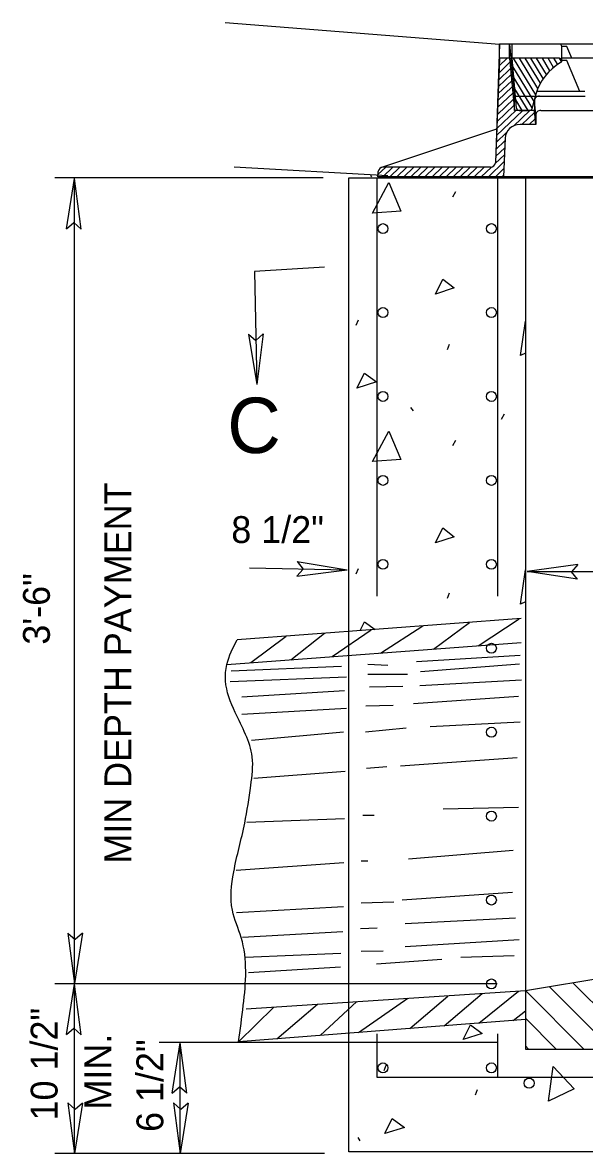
# Model space of a CAD drawing. Extents: x 0.9 to 8.1, y 0.4 to 10.5.
# Drawn here: x 0.924 to 1.927, y 5.374 to 7.395 of the extents above; entities that cross this region are included whole.
import ezdxf

# ---------------------------------------------------------------- set-up
doc = ezdxf.new("R2010")
doc.units = 0
for name, color, linetype in [('DETL-DIMS', 7, 'Continuous'), ('DETL-LINE', 7, 'Continuous'), ('DETL-NOTE', 7, 'Continuous')]:
    doc.layers.add(name, color=color, linetype=linetype)

msp = doc.modelspace()

# ---------------------------------------------------------------- linework, layer by layer
at = {"layer": 'DETL-DIMS'}
for p, q in [((1.4607, 7.1175), (0.9813, 7.1175)), ((1.002, 7.0264), (1.0163, 7.1162)), ((1.0163, 5.374), (1.0163, 7.1175)), ((1.0282, 7.026), (1.0163, 7.1162)), ((1.002, 7.0264), (1.0152, 7.0375)), ((1.0282, 7.026), (1.0152, 7.0375)), ((1.4629, 6.9579), (1.338, 6.9499)), ((1.338, 6.9499), (1.342, 6.7483)), ((1.3271, 6.8381), (1.342, 6.7483)), ((1.3271, 6.8381), (1.3405, 6.8271)), ((1.3534, 6.8386), (1.3405, 6.8271)), ((1.3534, 6.8386), (1.342, 6.7483)), ((1.414, 6.4318), (1.5038, 6.4168)), ((1.414, 6.4318), (1.425, 6.4184)), ((1.329, 6.4204), (1.5037, 6.4168)), ((1.4134, 6.4055), (1.425, 6.4184)), ((1.4134, 6.4055), (1.5038, 6.4168)), ((1.9155, 6.4263), (1.8254, 6.4138)), ((1.9153, 6.4), (1.8254, 6.4138)), ((1.8254, 6.4138), (3.481, 6.4138)), ((1.9155, 6.4263), (1.9042, 6.4132)), ((1.9153, 6.4), (1.9042, 6.4132)), ((1.0044, 5.7678), (1.0163, 5.6776)), ((1.0044, 5.7678), (1.0174, 5.7563)), ((1.0306, 5.7674), (1.0163, 5.6776)), ((1.0306, 5.7674), (1.0174, 5.7563)), ((0.9813, 5.6776), (1.7718, 5.6776)), ((1.002, 5.5864), (1.0163, 5.6763)), ((1.0282, 5.5861), (1.0163, 5.6763)), ((1.002, 5.5864), (1.0152, 5.5975)), ((1.0282, 5.5861), (1.0152, 5.5975)), ((1.1676, 5.573), (1.7718, 5.573)), ((1.1908, 5.4819), (1.2052, 5.5717)), ((1.2051, 5.374), (1.2051, 5.573)), ((1.2171, 5.4815), (1.2052, 5.5717)), ((1.1908, 5.4819), (1.2041, 5.4929)), ((1.2171, 5.4815), (1.2041, 5.4929)), ((1.0044, 5.4642), (1.0163, 5.374)), ((1.0044, 5.4642), (1.0174, 5.4527)), ((1.0306, 5.4638), (1.0163, 5.374)), ((1.0306, 5.4638), (1.0174, 5.4527)), ((1.1932, 5.4642), (1.2051, 5.374)), ((1.1932, 5.4642), (1.2062, 5.4527)), ((1.2195, 5.4638), (1.2051, 5.374)), ((1.2195, 5.4638), (1.2062, 5.4527)), ((1.4629, 5.374), (0.9813, 5.374))]:
    msp.add_line(p, q, dxfattribs=at)
at = {"layer": 'DETL-LINE'}
for p, q in [((1.2854, 7.395), (1.776, 7.3567)), ((1.776, 7.3567), (1.7683, 7.1447)), ((1.7982, 7.3567), (1.776, 7.3567)), ((1.7938, 7.3313), (1.7938, 7.3567)), ((1.7938, 7.3567), (1.8023, 7.2636)), ((1.8827, 7.3567), (1.7982, 7.3567)), ((1.7982, 7.3313), (1.7982, 7.3567)), ((2.6296, 7.3567), (1.8827, 7.3567)), ((1.8871, 7.3271), (1.8871, 7.3525)), ((1.896, 7.3525), (1.8871, 7.3525)), ((1.905, 7.3313), (1.896, 7.3525)), ((1.7749, 7.3055), (1.7944, 7.3241)), ((1.7754, 7.3179), (1.7895, 7.3313)), ((1.7759, 7.3304), (1.7769, 7.3313)), ((1.7938, 7.3313), (1.776, 7.3313)), ((1.7938, 7.3313), (1.8023, 7.2382)), ((1.8064, 7.242), (1.7982, 7.3313)), ((1.8827, 7.3313), (1.7982, 7.3313)), ((1.8375, 7.2543), (1.7995, 7.3168)), ((1.8406, 7.266), (1.801, 7.3313)), ((1.8442, 7.277), (1.8113, 7.3313)), ((1.8487, 7.2865), (1.8216, 7.3313)), ((1.8539, 7.2949), (1.8318, 7.3313)), ((1.8596, 7.3024), (1.8421, 7.3313)), ((1.8659, 7.3091), (1.8524, 7.3313)), ((1.8725, 7.315), (1.8626, 7.3313)), ((1.8797, 7.3202), (1.8729, 7.3313)), ((1.8868, 7.3254), (1.8832, 7.3313)), ((2.0072, 7.3313), (1.8871, 7.3313)), ((1.896, 7.3271), (1.8871, 7.3271)), ((1.9192, 7.272), (1.896, 7.3271)), ((1.7739, 7.2806), (1.7965, 7.302)), ((1.7744, 7.293), (1.7954, 7.313)), ((1.8343, 7.2426), (1.8014, 7.2969)), ((1.7729, 7.2556), (1.7985, 7.28)), ((1.7734, 7.2681), (1.7975, 7.291)), ((1.8267, 7.2382), (1.8032, 7.2769)), ((1.7719, 7.2307), (1.8005, 7.258)), ((1.7724, 7.2432), (1.7995, 7.269)), ((1.8023, 7.2382), (1.8023, 7.2636)), ((1.8044, 7.2636), (1.8023, 7.2636)), ((1.8044, 7.2635), (1.84, 7.2635)), ((1.8164, 7.2382), (1.805, 7.2569)), ((1.8339, 7.2413), (1.841, 7.2671)), ((1.84, 7.2635), (1.9289, 7.2635)), ((1.9281, 7.272), (1.8424, 7.272)), ((1.7703, 7.1933), (1.8174, 7.2382)), ((1.7709, 7.2058), (1.8048, 7.2382)), ((1.7714, 7.2183), (1.8015, 7.247)), ((1.8006, 7.2101), (1.83, 7.2382)), ((1.8381, 7.2382), (1.8023, 7.2382)), ((1.8108, 7.2382), (1.8296, 7.2382)), ((1.8404, 7.2297), (1.8381, 7.2551)), ((1.8381, 7.2551), (1.8381, 7.2382)), ((1.8404, 7.2128), (1.8381, 7.2382)), ((1.8493, 7.2381), (3.4632, 7.2381)), ((1.8159, 7.2128), (1.8385, 7.2343)), ((1.8285, 7.2128), (1.8395, 7.2233)), ((1.8404, 7.2297), (1.8404, 7.2128)), ((1.7705, 7.2043), (1.5649, 7.1361)), ((1.7698, 7.1809), (1.7885, 7.1986)), ((1.8404, 7.2128), (1.8124, 7.2128)), ((1.7693, 7.1684), (1.7855, 7.1838)), ((1.7857, 7.1883), (1.7829, 7.1196)), ((1.7682, 7.1434), (1.7845, 7.1589)), ((1.7688, 7.156), (1.785, 7.1714)), ((1.3018, 7.137), (1.5761, 7.1216)), ((1.5585, 7.1233), (1.5724, 7.1365)), ((1.5672, 7.1196), (1.585, 7.1365)), ((1.7595, 7.1365), (1.5678, 7.1365)), ((1.5798, 7.1196), (1.5975, 7.1365)), ((1.5923, 7.1196), (1.6101, 7.1365)), ((1.6049, 7.1196), (1.6227, 7.1365)), ((1.6175, 7.1196), (1.6353, 7.1365)), ((1.6301, 7.1196), (1.6478, 7.1365)), ((1.6426, 7.1196), (1.6604, 7.1365)), ((1.6552, 7.1196), (1.673, 7.1365)), ((1.6678, 7.1196), (1.6856, 7.1365)), ((1.6804, 7.1196), (1.6981, 7.1365)), ((1.6929, 7.1196), (1.7107, 7.1365)), ((1.7055, 7.1196), (1.7233, 7.1365)), ((1.7181, 7.1196), (1.7359, 7.1365)), ((1.7307, 7.1196), (1.7484, 7.1365)), ((1.7432, 7.1196), (1.7612, 7.1367)), ((1.7558, 7.1196), (1.784, 7.1465)), ((1.5478, 7.1196), (1.5458, 7.1215)), ((1.5581, 7.1196), (1.559, 7.1288)), ((1.7829, 7.1196), (1.5581, 7.1196)), ((1.7684, 7.1196), (1.7835, 7.134)), ((1.781, 7.1196), (1.783, 7.1215)), ((3.5296, 7.1196), (1.7829, 7.1196)), ((1.8221, 7.1175), (1.8221, 5.5604)), ((1.6926, 7.0837), (1.6975, 7.0934)), ((1.5199, 6.8542), (1.5236, 6.8639)), ((1.683, 6.8108), (1.6866, 6.8204)), ((1.8221, 6.804), (1.8134, 6.7999)), ((1.6165, 6.7069), (1.6214, 6.7009)), ((1.7796, 6.6864), (1.7844, 6.696)), ((1.6926, 6.6393), (1.6975, 6.6489)), ((1.5199, 6.4098), (1.5236, 6.4195)), ((1.683, 6.3663), (1.6866, 6.376)), ((1.8221, 6.3596), (1.8134, 6.3555)), ((1.8146, 6.3298), (1.307, 6.2919)), ((1.7374, 6.2813), (1.8106, 6.3295)), ((1.4765, 6.2618), (1.5464, 6.3098)), ((1.5066, 5.5888), (1.5066, 6.3068)), ((1.5629, 6.2683), (1.6385, 6.3167)), ((1.6579, 6.2754), (1.7223, 6.3229)), ((1.2886, 6.2479), (1.8146, 6.287)), ((1.3316, 6.2511), (1.3948, 6.2985)), ((1.4029, 6.2564), (1.4629, 6.3036)), ((1.5403, 6.2486), (1.5763, 6.2465)), ((1.6272, 6.2529), (1.8127, 6.2645)), ((1.8117, 6.2486), (1.6346, 6.2348)), ((1.5021, 6.2253), (1.2943, 6.2168)), ((1.4936, 6.2444), (1.2964, 6.2359)), ((1.5403, 6.2306), (1.6113, 6.2306)), ((1.6028, 6.2083), (1.5434, 6.2072)), ((1.8149, 6.22), (1.6336, 6.2094)), ((1.4989, 6.2009), (1.3155, 6.1892)), ((1.8096, 6.1903), (1.6219, 6.1775)), ((1.5021, 6.1691), (1.3155, 6.1585)), ((1.5858, 6.1744), (1.5371, 6.1733)), ((1.8127, 6.1447), (1.6516, 6.1362)), ((1.4968, 6.1266), (1.3324, 6.1118)), ((1.6092, 6.1341), (1.536, 6.1266)), ((1.5742, 6.0651), (1.5381, 6.0619)), ((1.8074, 6.081), (1.5986, 6.0662)), ((1.5, 6.0566), (1.3367, 6.0439)), ((1.6749, 5.9898), (1.8096, 5.993)), ((1.4989, 5.9718), (1.324, 5.9654)), ((1.5519, 5.9781), (1.5318, 5.9781)), ((1.8221, 5.665), (3.4886, 5.9414)), ((1.8, 5.9155), (1.6134, 5.8996)), ((1.4978, 5.8933), (1.3049, 5.8795)), ((1.5403, 5.8964), (1.5286, 5.8964)), ((1.5869, 5.8232), (1.5286, 5.8211)), ((1.799, 5.8402), (1.6017, 5.8264)), ((1.4968, 5.8148), (1.3059, 5.8041)), ((1.8043, 5.7946), (1.607, 5.784)), ((1.4957, 5.7702), (1.3165, 5.7596)), ((1.5572, 5.7766), (1.5275, 5.7755)), ((1.607, 5.7437), (1.8106, 5.7564)), ((1.3218, 5.7246), (1.4925, 5.732)), ((1.5286, 5.7352), (1.5678, 5.7363)), ((1.5562, 5.7129), (1.6728, 5.7214)), ((1.7067, 5.7246), (1.8021, 5.7278)), ((1.3271, 5.697), (1.4915, 5.7076)), ((1.3229, 5.6323), (1.8221, 5.665)), ((1.6771, 5.6019), (1.745, 5.6599)), ((1.7387, 5.6066), (1.8097, 5.6641)), ((1.8221, 5.665), (1.9267, 5.5604)), ((1.8646, 5.672), (1.9762, 5.5604)), ((1.907, 5.679), (2.0257, 5.5604)), ((1.3776, 5.5788), (1.4505, 5.6407)), ((1.4554, 5.5848), (1.5209, 5.6453)), ((1.5239, 5.5901), (1.6122, 5.6512)), ((1.6155, 5.5972), (1.6834, 5.6552)), ((1.3094, 5.5736), (1.3727, 5.6356)), ((1.8003, 5.6114), (1.8221, 5.629)), ((1.8221, 5.6131), (1.3094, 5.5736)), ((1.8221, 5.6155), (1.8772, 5.5604)), ((1.5566, 5.5875), (1.5566, 5.5104)), ((1.7721, 5.5875), (1.7721, 5.5104)), ((1.8221, 5.566), (1.8277, 5.5604)), ((1.8221, 5.5604), (3.4886, 5.5604)), ((1.5695, 5.5219), (1.5732, 5.5315)), ((1.5566, 5.5104), (1.7721, 5.5104)), ((1.7721, 5.5104), (3.5386, 5.5104)), ((1.7326, 5.4784), (1.7362, 5.4881)), ((1.5224, 5.4023), (1.5261, 5.3963))]:
    msp.add_line(p, q, dxfattribs=at)
for points in [[(1.5066, 6.3068), (1.5066, 7.1175), (3.7698, 7.1175), (3.7698, 5.3767), (1.5066, 5.3767), (1.5066, 5.5888)], [(1.5566, 7.1175), (1.5566, 6.3698)], [(1.7721, 7.1175), (1.7721, 6.3698)], [(1.5489, 7.0547), (1.5779, 7.1091), (1.5996, 7.0583), (1.5489, 7.0547)], [(1.6612, 6.9098), (1.6745, 6.9364), (1.695, 6.9207), (1.6612, 6.9098)], [(1.8134, 6.7999), (1.8219, 6.8615), (1.8221, 6.8612)], [(1.5211, 6.7419), (1.5344, 6.7685), (1.5562, 6.7528), (1.5211, 6.7419)], [(1.5489, 6.6103), (1.5779, 6.6646), (1.5996, 6.6139), (1.5489, 6.6103)], [(1.6612, 6.4654), (1.6745, 6.4919), (1.695, 6.4762), (1.6612, 6.4654)], [(1.8134, 6.3555), (1.8219, 6.417), (1.8221, 6.4168)], [(1.5266, 6.3084), (1.5344, 6.3241), (1.5533, 6.3104)], [(1.7108, 5.5774), (1.7241, 5.604), (1.7447, 5.5883), (1.7108, 5.5774)], [(1.863, 5.4675), (1.8715, 5.5291), (1.9089, 5.4893), (1.863, 5.4675)], [(1.5707, 5.4096), (1.584, 5.4361), (1.6058, 5.4204), (1.5707, 5.4096)]]:
    msp.add_lwpolyline(points, dxfattribs=at)
for centre in [(1.5675, 7.0268), (1.7613, 7.0268), (1.5675, 6.8768), (1.7613, 6.8768), (1.5675, 6.7268), (1.7613, 6.7268), (1.5675, 6.5768), (1.7613, 6.5768), (1.5675, 6.4268), (1.7613, 6.4268), (1.7613, 6.2768), (1.7613, 6.1268), (1.7613, 5.9768), (1.7613, 5.8268), (1.7613, 5.6768), (1.5675, 5.5268), (1.7613, 5.5268), (1.8287, 5.4995)]:
    msp.add_circle(centre, 0.00888, dxfattribs=at)
for centre, major_axis, start_param, end_param in [((1.8827, 7.3525), (0.00445, 0), 0, 1.570796), ((1.9356, 7.2438), (0.0978, 0), 2.115265, 2.888349), ((1.8827, 7.3271), (0.00445, 0), 5.256857, 7.853982), ((1.847, 7.2551), (0.00889, 0), 1.570796, 3.141593), ((1.8108, 7.2424), (0.00445, 0), 3.228859, 4.712348), ((1.8296, 7.2424), (0.00445, 0), 4.712348, 6.029942), ((1.8493, 7.2297), (0.00889, 0), 1.570796, 3.141593), ((1.8124, 7.1874), (0.0267, 0), 1.570796, 3.102737), ((1.5678, 7.1281), (0.00889, 0), 1.570796, 3.054326), ((1.7595, 7.145), (0.00889, 0), 4.712389, 6.24433)]:
    msp.add_ellipse(centre, major_axis=major_axis, ratio=0.952381, start_param=start_param, end_param=end_param, dxfattribs=at)
msp.add_spline([(1.3094, 5.5736), (1.318, 5.6385), (1.3143, 5.7596), (1.2984, 5.8085), (1.3009, 5.8771), (1.3204, 5.964), (1.3314, 6.0313), (1.3339, 6.0827), (1.3033, 6.1622), (1.2862, 6.2185), (1.2886, 6.2479), (1.307, 6.2919)], degree=3, dxfattribs=at)
at = {"layer": 'DETL-NOTE'}
for q in [(1.776, 7.3567), (1.7684, 7.1447)]:
    msp.add_line((1.776, 7.3313), q, dxfattribs=at)

# ---------------------------------------------------------------- texts
for s, height, p in [('C', 0.099, (1.2893, 6.6257)), ('8 1/2"', 0.048, (1.2965, 6.4649))]:
    msp.add_text(s, height=height, dxfattribs=at).set_placement(p)
for s, p in [('MIN DEPTH PAYMENT', (1.1178, 5.8918)), ('3\'-6"', (0.9723, 6.2832)), ('10 1/2"', (0.9861, 5.4329)), ('MIN.', (1.0821, 5.4525)), ('6 1/2"', (1.175, 5.4123))]:
    msp.add_text(s, height=0.048, rotation=90, dxfattribs=at).set_placement(p)

doc.saveas('drawing.dxf')
